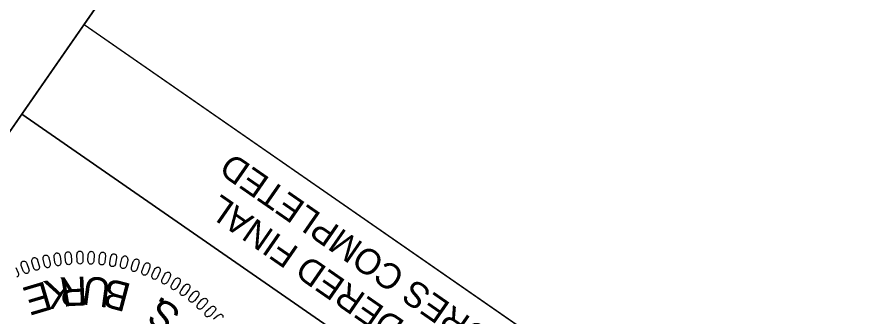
# Model space of a CAD drawing. Extents: x 478372 to 480379, y 492840 to 494699.
# Drawn here: x 478483.3 to 478667.1, y 493887.7 to 493952.4 of the extents above; entities that cross this region are included whole.
import ezdxf

# ---------------------------------------------------------------- set-up
doc = ezdxf.new("R2010")
doc.units = 0
for name, color, linetype in [('Sheet Clip Boundary CELL', 7, 'Continuous'), ('Sheet PE Seal Cell', 7, 'Continuous'), ('Sheet Plan CELL', 7, 'Continuous'), ('Sheet Sticker Exception Certification CELL', 7, 'Continuous')]:
    doc.layers.add(name, color=color, linetype=linetype)

msp = doc.modelspace()

# ---------------------------------------------------------------- linework, layer by layer
at = {"layer": 'Sheet Clip Boundary CELL'}
msp.add_lwpolyline([(479740.65, 493110.71), (479819.09, 493331.13), (479938.9, 493670.6), (480035.01, 493951.06), (479137.46, 494573.68), (479091.85, 494507.93), (479078.63, 494420.53), (478968.98, 494336.48), (478682.91, 494117.93), (478570.32, 494055.33), (478497.76, 493950.74), (478662.13, 493836.73), (478563.21, 493694.11), (479631.38, 492953.18)], close=True, dxfattribs=at)
at = {"layer": 'Sheet PE Seal Cell'}
for points in [[(478496.26, 493899.9), (478496.23, 493901.13), (478496.26, 493901.35), (478496.31, 493901.49), (478496.42, 493901.66), (478496.52, 493901.77), (478496.63, 493901.86), (478496.73, 493901.9), (478496.84, 493901.92), (478496.95, 493901.9), (478497.07, 493901.87), (478497.18, 493901.82), (478497.29, 493901.72), (478497.35, 493901.64), (478497.42, 493901.49), (478497.48, 493901.32), (478497.51, 493901.16), (478497.54, 493899.9), (478497.52, 493899.73), (478497.48, 493899.59), (478497.4, 493899.43), (478497.29, 493899.29), (478497.19, 493899.2), (478497.04, 493899.14), (478496.89, 493899.12), (478496.74, 493899.15), (478496.63, 493899.2), (478496.5, 493899.3), (478496.38, 493899.47), (478496.31, 493899.64), (478496.28, 493899.77)], [(478486.87, 493898.38), (478486.54, 493899.56), (478486.52, 493899.78), (478486.53, 493899.93), (478486.59, 493900.13), (478486.66, 493900.26), (478486.74, 493900.36), (478486.83, 493900.43), (478486.94, 493900.48), (478487.05, 493900.49), (478487.17, 493900.49), (478487.29, 493900.47), (478487.42, 493900.4), (478487.5, 493900.34), (478487.6, 493900.21), (478487.71, 493900.05), (478487.77, 493899.91), (478488.12, 493898.7), (478488.14, 493898.53), (478488.14, 493898.38), (478488.09, 493898.21), (478488.02, 493898.04), (478487.95, 493897.94), (478487.81, 493897.84), (478487.68, 493897.78), (478487.52, 493897.78), (478487.41, 493897.8), (478487.26, 493897.86), (478487.1, 493897.99), (478486.98, 493898.14), (478486.92, 493898.26)], [(478489.21, 493898.96), (478488.96, 493900.16), (478488.95, 493900.38), (478488.97, 493900.53), (478489.04, 493900.72), (478489.12, 493900.85), (478489.21, 493900.95), (478489.3, 493901.01), (478489.41, 493901.05), (478489.52, 493901.06), (478489.65, 493901.05), (478489.76, 493901.02), (478489.88, 493900.94), (478489.96, 493900.87), (478490.06, 493900.74), (478490.15, 493900.58), (478490.21, 493900.43), (478490.48, 493899.2), (478490.49, 493899.03), (478490.48, 493898.88), (478490.42, 493898.71), (478490.34, 493898.55), (478490.26, 493898.45), (478490.12, 493898.36), (478489.98, 493898.31), (478489.82, 493898.32), (478489.71, 493898.34), (478489.57, 493898.41), (478489.41, 493898.55), (478489.31, 493898.72), (478489.25, 493898.84)], [(478491.5, 493899.43), (478491.32, 493900.65), (478491.33, 493900.87), (478491.36, 493901.02), (478491.45, 493901.2), (478491.53, 493901.32), (478491.63, 493901.42), (478491.72, 493901.47), (478491.83, 493901.51), (478491.94, 493901.51), (478492.07, 493901.49), (478492.18, 493901.45), (478492.3, 493901.37), (478492.37, 493901.3), (478492.46, 493901.16), (478492.54, 493900.99), (478492.59, 493900.83), (478492.78, 493899.59), (478492.78, 493899.42), (478492.76, 493899.28), (478492.69, 493899.11), (478492.6, 493898.95), (478492.52, 493898.86), (478492.37, 493898.78), (478492.23, 493898.73), (478492.07, 493898.75), (478491.96, 493898.79), (478491.82, 493898.87), (478491.68, 493899.02), (478491.59, 493899.18), (478491.54, 493899.31)], [(478493.8, 493899.7), (478493.7, 493900.93), (478493.71, 493901.15), (478493.75, 493901.29), (478493.85, 493901.47), (478493.94, 493901.59), (478494.04, 493901.68), (478494.15, 493901.72), (478494.26, 493901.75), (478494.37, 493901.74), (478494.49, 493901.72), (478494.6, 493901.67), (478494.71, 493901.58), (478494.78, 493901.51), (478494.86, 493901.36), (478494.93, 493901.19), (478494.97, 493901.03), (478495.08, 493899.78), (478495.07, 493899.61), (478495.04, 493899.47), (478494.97, 493899.3), (478494.87, 493899.15), (478494.77, 493899.06), (478494.62, 493898.99), (478494.48, 493898.96), (478494.32, 493898.99), (478494.22, 493899.03), (478494.08, 493899.12), (478493.95, 493899.27), (478493.86, 493899.45), (478493.82, 493899.58)], [(478498.61, 493899.89), (478498.66, 493901.11), (478498.71, 493901.33), (478498.77, 493901.47), (478498.89, 493901.63), (478498.99, 493901.74), (478499.1, 493901.81), (478499.21, 493901.85), (478499.32, 493901.86), (478499.43, 493901.84), (478499.55, 493901.8), (478499.65, 493901.74), (478499.75, 493901.64), (478499.81, 493901.55), (478499.87, 493901.4), (478499.92, 493901.22), (478499.94, 493901.06), (478499.9, 493899.8), (478499.87, 493899.63), (478499.81, 493899.5), (478499.72, 493899.34), (478499.6, 493899.21), (478499.5, 493899.13), (478499.34, 493899.08), (478499.19, 493899.06), (478499.04, 493899.11), (478498.94, 493899.16), (478498.82, 493899.27), (478498.71, 493899.44), (478498.65, 493899.63), (478498.62, 493899.76)], [(478500.99, 493899.77), (478501.11, 493900.99), (478501.17, 493901.2), (478501.24, 493901.34), (478501.37, 493901.49), (478501.48, 493901.59), (478501.6, 493901.66), (478501.71, 493901.69), (478501.82, 493901.7), (478501.93, 493901.66), (478502.04, 493901.62), (478502.14, 493901.55), (478502.24, 493901.44), (478502.29, 493901.36), (478502.34, 493901.2), (478502.38, 493901.02), (478502.39, 493900.85), (478502.26, 493899.6), (478502.22, 493899.44), (478502.16, 493899.3), (478502.06, 493899.15), (478501.93, 493899.03), (478501.83, 493898.96), (478501.66, 493898.91), (478501.51, 493898.91), (478501.37, 493898.97), (478501.27, 493899.03), (478501.15, 493899.14), (478501.05, 493899.32), (478501, 493899.51), (478500.99, 493899.64)], [(478503.32, 493899.44), (478503.52, 493900.65), (478503.6, 493900.86), (478503.67, 493900.99), (478503.81, 493901.14), (478503.92, 493901.23), (478504.05, 493901.29), (478504.16, 493901.31), (478504.27, 493901.32), (478504.38, 493901.28), (478504.49, 493901.23), (478504.59, 493901.15), (478504.67, 493901.04), (478504.72, 493900.95), (478504.76, 493900.79), (478504.79, 493900.6), (478504.78, 493900.44), (478504.58, 493899.2), (478504.53, 493899.04), (478504.46, 493898.91), (478504.35, 493898.76), (478504.22, 493898.64), (478504.11, 493898.58), (478503.94, 493898.55), (478503.79, 493898.55), (478503.65, 493898.62), (478503.56, 493898.69), (478503.45, 493898.8), (478503.36, 493898.99), (478503.32, 493899.18), (478503.31, 493899.31)], [(478505.64, 493899.06), (478505.92, 493900.25), (478506.01, 493900.46), (478506.09, 493900.58), (478506.24, 493900.72), (478506.36, 493900.81), (478506.49, 493900.86), (478506.6, 493900.87), (478506.71, 493900.87), (478506.81, 493900.82), (478506.92, 493900.77), (478507.01, 493900.68), (478507.09, 493900.56), (478507.13, 493900.47), (478507.16, 493900.31), (478507.18, 493900.12), (478507.17, 493899.96), (478506.89, 493898.74), (478506.83, 493898.58), (478506.75, 493898.45), (478506.63, 493898.32), (478506.49, 493898.2), (478506.37, 493898.15), (478506.21, 493898.13), (478506.06, 493898.14), (478505.92, 493898.21), (478505.83, 493898.29), (478505.73, 493898.41), (478505.65, 493898.6), (478505.63, 493898.8), (478505.63, 493898.93)], [(478508.01, 493898.46), (478508.37, 493899.63), (478508.47, 493899.83), (478508.56, 493899.95), (478508.71, 493900.08), (478508.84, 493900.16), (478508.97, 493900.2), (478509.08, 493900.21), (478509.19, 493900.19), (478509.3, 493900.14), (478509.4, 493900.08), (478509.48, 493899.99), (478509.56, 493899.87), (478509.59, 493899.77), (478509.61, 493899.61), (478509.62, 493899.42), (478509.59, 493899.26), (478509.24, 493898.06), (478509.17, 493897.9), (478509.08, 493897.78), (478508.95, 493897.65), (478508.8, 493897.55), (478508.69, 493897.5), (478508.52, 493897.49), (478508.37, 493897.52), (478508.24, 493897.6), (478508.15, 493897.68), (478508.06, 493897.81), (478508, 493898), (478507.98, 493898.2), (478507.99, 493898.33)], [(478484.64, 493897.64), (478484.24, 493898.79), (478484.2, 493899.01), (478484.21, 493899.16), (478484.26, 493899.36), (478484.31, 493899.5), (478484.39, 493899.61), (478484.48, 493899.68), (478484.58, 493899.74), (478484.69, 493899.75), (478484.81, 493899.77), (478484.93, 493899.74), (478485.06, 493899.68), (478485.15, 493899.63), (478485.26, 493899.51), (478485.37, 493899.36), (478485.45, 493899.22), (478485.87, 493898.03), (478485.9, 493897.86), (478485.91, 493897.72), (478485.88, 493897.54), (478485.82, 493897.37), (478485.75, 493897.26), (478485.62, 493897.15), (478485.49, 493897.09), (478485.33, 493897.07), (478485.22, 493897.09), (478485.06, 493897.14), (478484.9, 493897.26), (478484.77, 493897.41), (478484.7, 493897.52)], [(478510.28, 493897.7), (478510.71, 493898.85), (478510.82, 493899.04), (478510.92, 493899.16), (478511.08, 493899.28), (478511.21, 493899.35), (478511.34, 493899.38), (478511.45, 493899.38), (478511.57, 493899.36), (478511.67, 493899.31), (478511.77, 493899.24), (478511.84, 493899.14), (478511.91, 493899.01), (478511.94, 493898.92), (478511.95, 493898.75), (478511.94, 493898.57), (478511.91, 493898.41), (478511.48, 493897.23), (478511.4, 493897.08), (478511.31, 493896.96), (478511.17, 493896.84), (478511.01, 493896.75), (478510.89, 493896.71), (478510.73, 493896.71), (478510.58, 493896.74), (478510.45, 493896.83), (478510.37, 493896.91), (478510.29, 493897.05), (478510.23, 493897.25), (478510.23, 493897.44), (478510.25, 493897.58)], [(478512.47, 493896.84), (478512.96, 493897.96), (478513.09, 493898.15), (478513.19, 493898.25), (478513.36, 493898.36), (478513.5, 493898.42), (478513.63, 493898.45), (478513.74, 493898.45), (478513.85, 493898.42), (478513.95, 493898.35), (478514.05, 493898.28), (478514.12, 493898.18), (478514.17, 493898.05), (478514.19, 493897.95), (478514.19, 493897.79), (478514.18, 493897.6), (478514.13, 493897.44), (478513.63, 493896.29), (478513.54, 493896.15), (478513.44, 493896.04), (478513.29, 493895.93), (478513.14, 493895.85), (478513.01, 493895.81), (478512.85, 493895.82), (478512.7, 493895.86), (478512.58, 493895.96), (478512.51, 493896.05), (478512.43, 493896.19), (478512.39, 493896.39), (478512.4, 493896.59), (478512.43, 493896.72)], [(478514.6, 493895.86), (478515.17, 493896.95), (478515.3, 493897.12), (478515.41, 493897.22), (478515.59, 493897.32), (478515.73, 493897.37), (478515.87, 493897.39), (478515.98, 493897.38), (478516.09, 493897.35), (478516.18, 493897.28), (478516.27, 493897.19), (478516.33, 493897.09), (478516.38, 493896.96), (478516.4, 493896.86), (478516.39, 493896.69), (478516.36, 493896.51), (478516.3, 493896.36), (478515.73, 493895.24), (478515.63, 493895.1), (478515.52, 493895), (478515.37, 493894.9), (478515.21, 493894.82), (478515.08, 493894.8), (478514.92, 493894.82), (478514.78, 493894.87), (478514.66, 493894.97), (478514.59, 493895.07), (478514.53, 493895.21), (478514.5, 493895.42), (478514.52, 493895.61), (478514.56, 493895.74)], [(478516.66, 493894.67), (478517.29, 493895.72), (478517.44, 493895.89), (478517.55, 493895.98), (478517.74, 493896.07), (478517.88, 493896.11), (478518.01, 493896.12), (478518.12, 493896.1), (478518.23, 493896.06), (478518.32, 493895.99), (478518.4, 493895.9), (478518.46, 493895.79), (478518.5, 493895.65), (478518.51, 493895.55), (478518.49, 493895.39), (478518.45, 493895.21), (478518.38, 493895.06), (478517.74, 493893.98), (478517.63, 493893.85), (478517.52, 493893.75), (478517.36, 493893.66), (478517.2, 493893.6), (478517.07, 493893.58), (478516.91, 493893.61), (478516.77, 493893.67), (478516.66, 493893.78), (478516.6, 493893.88), (478516.54, 493894.03), (478516.52, 493894.24), (478516.56, 493894.43), (478516.6, 493894.55)], [(478518.67, 493893.42), (478519.37, 493894.43), (478519.53, 493894.59), (478519.65, 493894.67), (478519.84, 493894.75), (478519.98, 493894.78), (478520.12, 493894.78), (478520.23, 493894.76), (478520.33, 493894.71), (478520.41, 493894.63), (478520.49, 493894.54), (478520.54, 493894.43), (478520.57, 493894.29), (478520.58, 493894.19), (478520.55, 493894.03), (478520.49, 493893.84), (478520.42, 493893.7), (478519.71, 493892.66), (478519.6, 493892.54), (478519.48, 493892.45), (478519.31, 493892.37), (478519.14, 493892.32), (478519.02, 493892.31), (478518.85, 493892.35), (478518.72, 493892.42), (478518.62, 493892.53), (478518.56, 493892.64), (478518.51, 493892.79), (478518.51, 493893), (478518.56, 493893.18), (478518.61, 493893.31)], [(478520.56, 493892.02), (478521.33, 493892.98), (478521.49, 493893.13), (478521.62, 493893.21), (478521.81, 493893.27), (478521.96, 493893.3), (478522.09, 493893.29), (478522.2, 493893.26), (478522.3, 493893.2), (478522.38, 493893.12), (478522.45, 493893.02), (478522.5, 493892.91), (478522.52, 493892.77), (478522.51, 493892.67), (478522.47, 493892.51), (478522.41, 493892.33), (478522.33, 493892.19), (478521.55, 493891.2), (478521.43, 493891.08), (478521.31, 493891), (478521.14, 493890.93), (478520.96, 493890.89), (478520.84, 493890.89), (478520.68, 493890.94), (478520.55, 493891.02), (478520.46, 493891.14), (478520.41, 493891.24), (478520.37, 493891.4), (478520.38, 493891.61), (478520.44, 493891.79), (478520.49, 493891.91)], [(478522.35, 493890.54), (478523.18, 493891.45), (478523.35, 493891.59), (478523.48, 493891.66), (478523.68, 493891.71), (478523.82, 493891.73), (478523.96, 493891.71), (478524.07, 493891.67), (478524.16, 493891.61), (478524.23, 493891.52), (478524.3, 493891.42), (478524.34, 493891.3), (478524.35, 493891.16), (478524.34, 493891.06), (478524.29, 493890.9), (478524.22, 493890.73), (478524.13, 493890.6), (478523.29, 493889.66), (478523.16, 493889.55), (478523.03, 493889.47), (478522.86, 493889.41), (478522.68, 493889.38), (478522.56, 493889.39), (478522.4, 493889.45), (478522.28, 493889.54), (478522.19, 493889.67), (478522.15, 493889.77), (478522.12, 493889.93), (478522.15, 493890.14), (478522.22, 493890.32), (478522.28, 493890.43)], [(478524.11, 493888.92), (478524.99, 493889.78), (478525.17, 493889.91), (478525.31, 493889.97), (478525.51, 493890.01), (478525.65, 493890.01), (478525.79, 493889.99), (478525.89, 493889.94), (478525.98, 493889.88), (478526.05, 493889.78), (478526.11, 493889.68), (478526.14, 493889.56), (478526.14, 493889.42), (478526.13, 493889.32), (478526.07, 493889.16), (478525.98, 493889), (478525.88, 493888.87), (478524.99, 493887.98), (478524.85, 493887.88), (478524.72, 493887.81), (478524.55, 493887.77), (478524.37, 493887.75), (478524.24, 493887.76), (478524.09, 493887.83), (478523.97, 493887.93), (478523.9, 493888.06), (478523.86, 493888.17), (478523.84, 493888.33), (478523.88, 493888.53), (478523.96, 493888.71), (478524.03, 493888.82)]]:
    msp.add_lwpolyline(points, close=True, dxfattribs=at)
for points in [[(478483.08, 493898.38), (478483.57, 493897.23), (478483.62, 493897.06), (478483.63, 493896.92), (478483.61, 493896.73), (478483.56, 493896.56), (478483.5, 493896.45), (478483.38, 493896.33), (478483.25, 493896.26)], [(478527.75, 493887.57), (478527.77, 493887.71), (478527.76, 493887.85), (478527.72, 493887.96), (478527.66, 493888.05), (478527.58, 493888.12), (478527.47, 493888.2), (478527.36, 493888.24), (478527.22, 493888.25), (478527.12, 493888.24), (478526.96, 493888.2), (478526.79, 493888.12), (478526.65, 493888.04), (478525.69, 493887.22)]]:
    msp.add_lwpolyline(points, dxfattribs=at)
at = {"layer": 'Sheet Plan CELL'}
for points in [[(478398.82, 493808.16), (479631.35, 492953.18), (480229.82, 493815.92), (478997.32, 494670.89)], [(480229.82, 493815.92), (479631.38, 492953.18), (478563.21, 493694.11), (478648.73, 493817.42), (478484.38, 493931.45), (478997.32, 494670.89)], [(478502.42, 493782.01), (478420.26, 493838.99), (478484.38, 493931.45), (478566.55, 493874.46)]]:
    msp.add_lwpolyline(points, close=True, dxfattribs=at)
at = {"layer": 'Sheet Sticker Exception Certification CELL'}
for p, q in [((478484.38, 493931.45), (478497.77, 493950.76)), ((478484.38, 493931.45), (478497.77, 493950.76)), ((478497.76, 493950.74), (478662.13, 493836.73)), ((478497.76, 493950.74), (478662.13, 493836.73)), ((478648.73, 493817.42), (478484.37, 493931.44)), ((478648.73, 493817.42), (478484.37, 493931.44))]:
    msp.add_line(p, q, dxfattribs=at)

# ---------------------------------------------------------------- texts
at = {"layer": 'Sheet PE Seal Cell'}
for s, rotation, p in [('R', 182.3992, (478498.3, 493896.45)), ('U', 172.2993, (478503.85, 493895.84)), ('E', 196.5199, (478489.56, 493895.49)), ('K', 189.6742, (478494.29, 493896.32)), ('B', 165.1825, (478508.22, 493894.74)), ('S', 144.6342, (478519.02, 493888.89)), ('.', 151.4799, (478515.73, 493891.23))]:
    msp.add_text(s, height=6.24, rotation=rotation, dxfattribs=at).set_placement(p)
at = {"layer": 'Sheet Sticker Exception Certification CELL'}
for s, p in [('UNLESS ALL SIGNATURES COMPLETED', (478646.5, 493842.27)), ('UNLESS ALL SIGNATURES COMPLETED', (478646.5, 493842.27)), ('DOCUMENT NOT CONSIDERED FINAL', (478637.32, 493837.93)), ('DOCUMENT NOT CONSIDERED FINAL', (478637.32, 493837.93))]:
    msp.add_text(s, height=5.5, rotation=145.2516, dxfattribs=at).set_placement(p)

doc.saveas('drawing.dxf')
